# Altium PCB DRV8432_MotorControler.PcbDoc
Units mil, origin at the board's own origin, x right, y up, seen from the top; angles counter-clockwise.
Board outline 2906.47 x 1828.55 mil, 2 copper layers (Top Layer, Bottom Layer); 56 components, 32 nets, 157 pads, 266 vias.
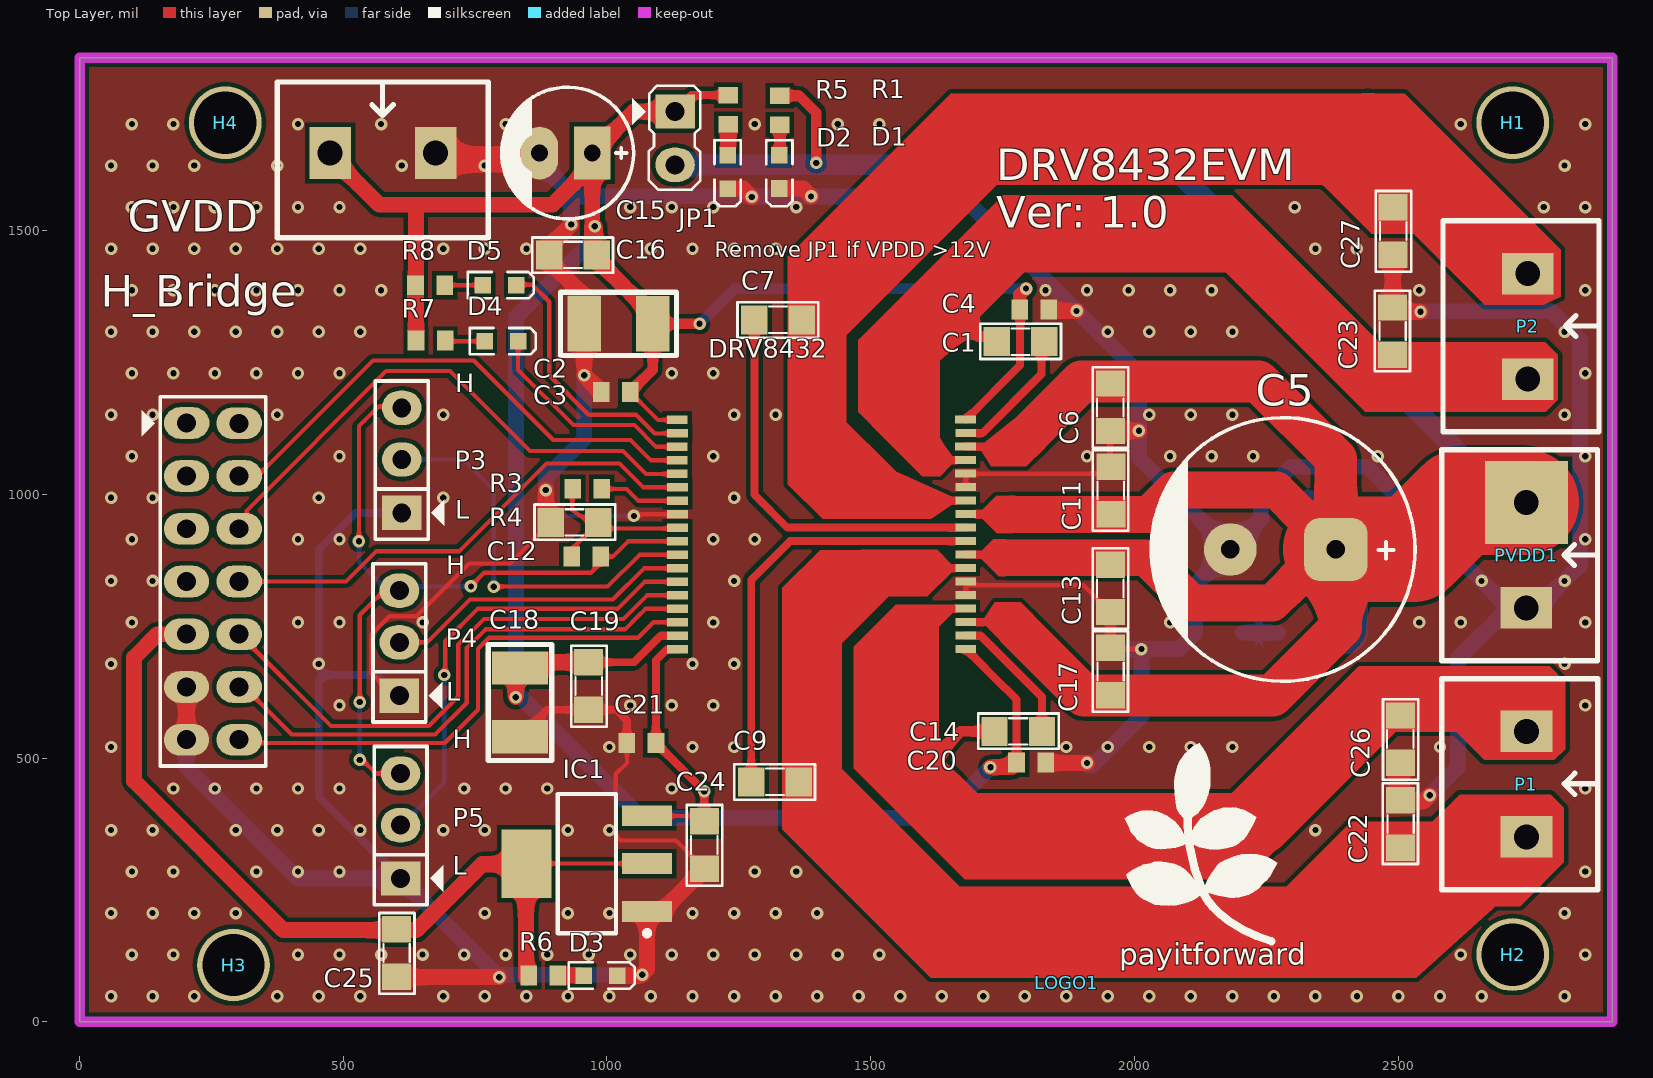
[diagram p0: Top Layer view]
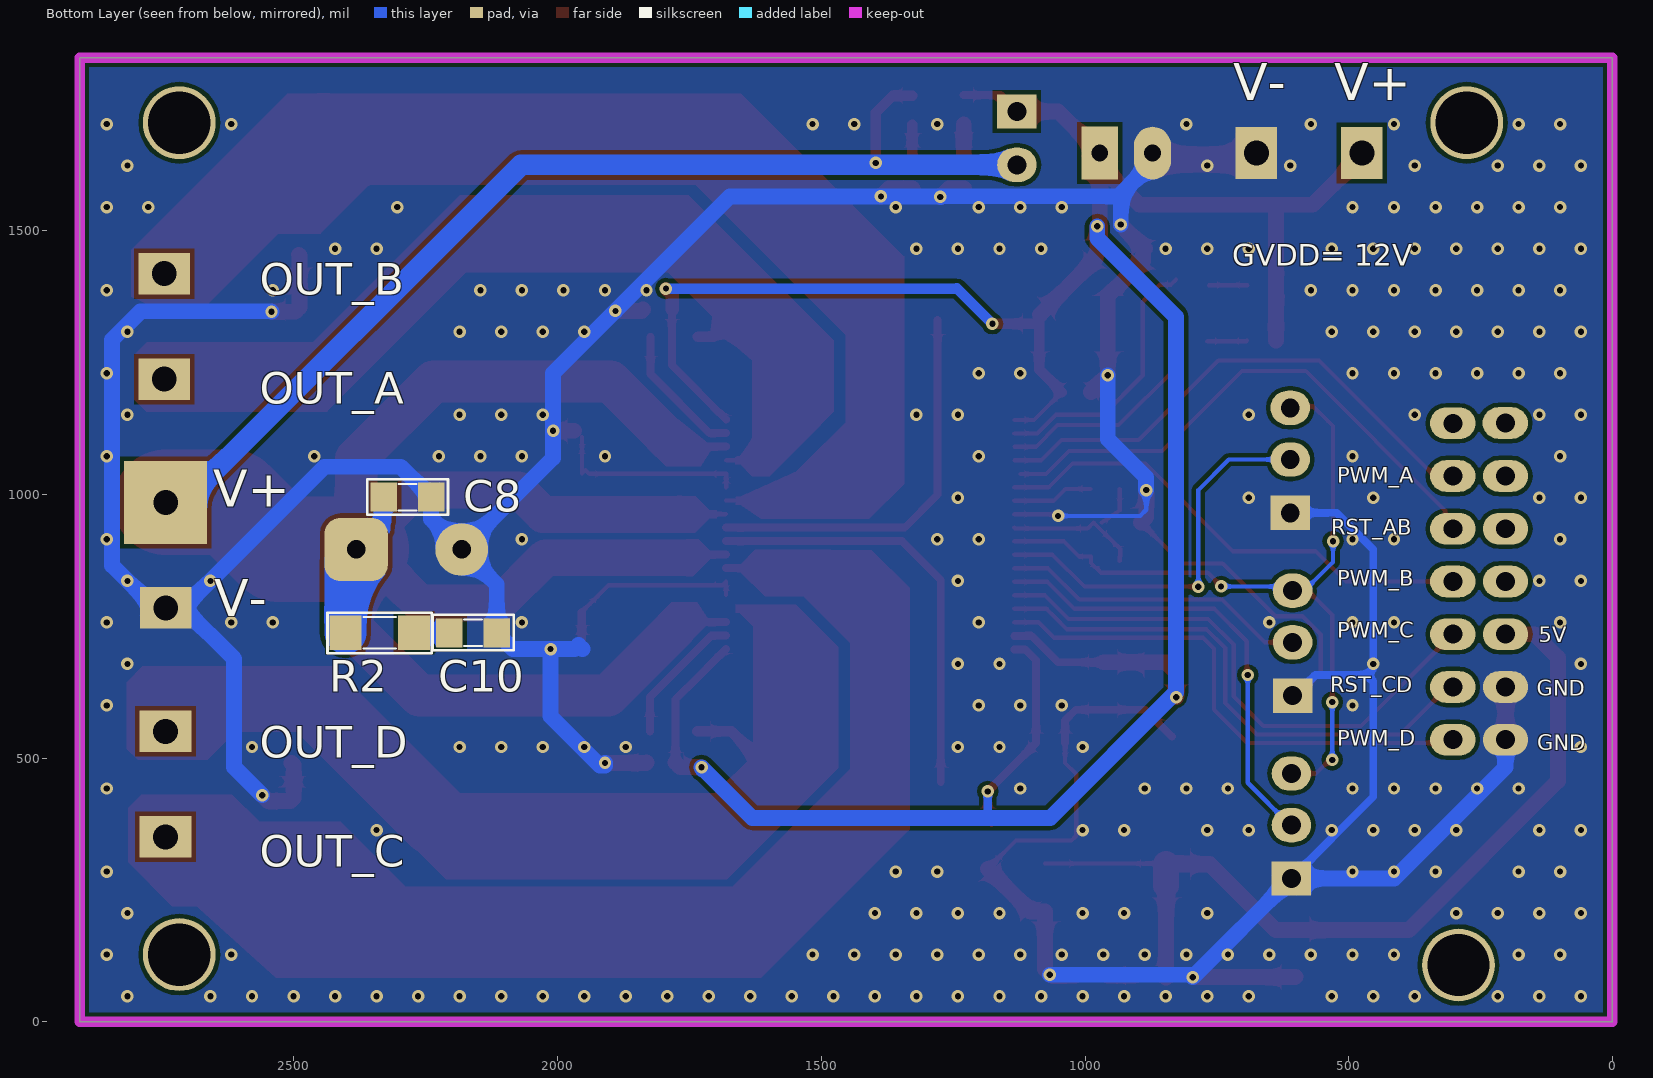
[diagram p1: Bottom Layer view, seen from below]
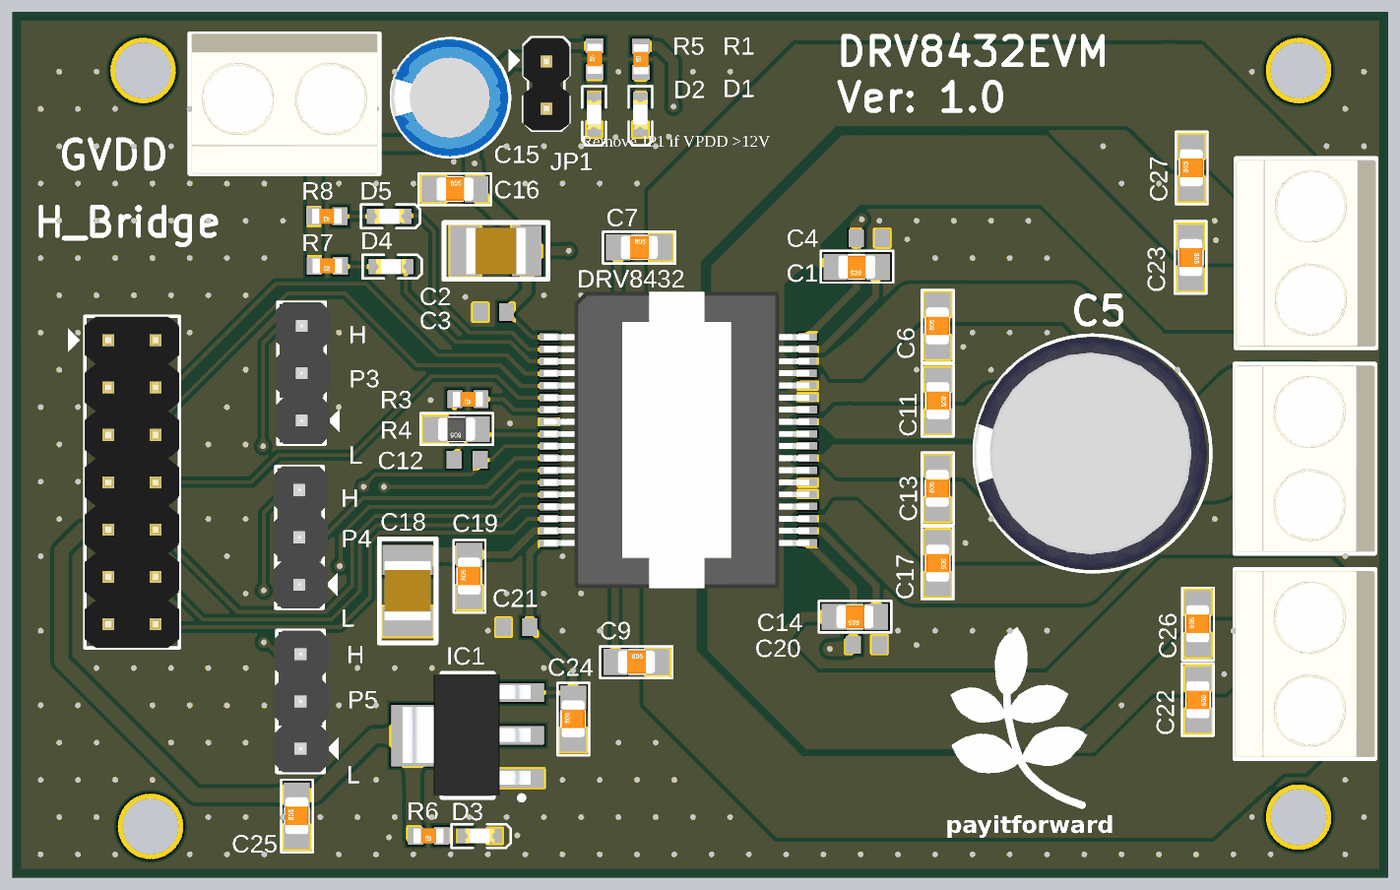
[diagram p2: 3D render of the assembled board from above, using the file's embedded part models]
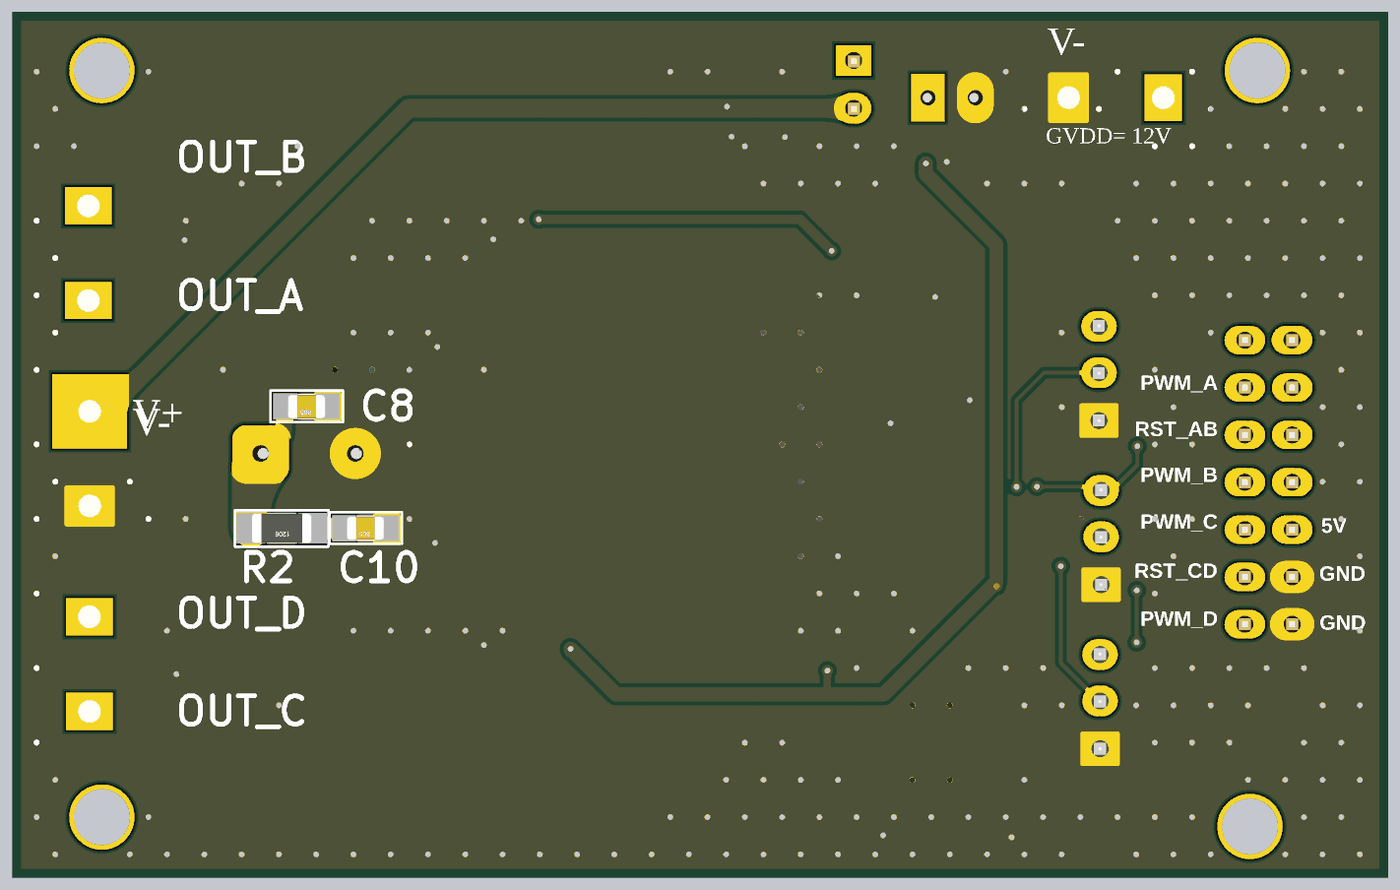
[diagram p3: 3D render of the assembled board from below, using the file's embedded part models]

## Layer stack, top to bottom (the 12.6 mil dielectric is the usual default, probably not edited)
Top Solder: solder mask 0.4, Solder Resist, Dk 3.5
Top Layer: signal copper 1.4
Dielectric 1: dielectric 12.6, FR-4, Dk 4.8
Bottom Layer: signal copper 1.4
Bottom Solder: solder mask 0.4, Solder Resist, Dk 3.5

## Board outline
0,0 2906.46,0 2906.46,1828.55 0,1828.55

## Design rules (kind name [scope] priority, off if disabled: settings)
Clearance [All] p1: gap=8 ignorepadtopadclearanceinfootprint=FALSE
PlaneConnect [All] p1: planeconnectstyle=Direct reliefexpansion=20 reliefentries=4 reliefconductorwidth=10 reliefairgap=10
PolygonConnect [All] p1: connectstyle=Direct reliefconductorwidth=10 reliefentries=4 polygonreliefangle="90 Angle" airgapwidth=10
RoutingVias [All] p1: holewidth=11.81 width=23.62 viastyle="Through Hole" minholewidth=11.81 minwidth=23.62 maxholewidth=196.85 maxwidth=196.85
SolderMaskExpansion [All] p1: expansion=4
Width [All] p1: maxlimit=200 minlimit=8 preferedwidth=15 minimp=50.000000 maximp=50.000000 favimp=50.000000
29 further rules are at their usual default settings.

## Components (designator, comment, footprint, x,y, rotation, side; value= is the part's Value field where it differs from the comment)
C1 "Cap Non-Pol SMD" CAP-SM-0805 1828.93,1289.91 r180 top value=0.1ufd/100V
C2 "Cap Non-Pol SMD" CAP-SM-1210 1021.79,1323.73 r0 top value=100nF
C3 "Cap Non-Pol SMD" CAP-SM-0603 1016.45,1194.2 r180 top value=1ufd/16v
C4 "Cap Non-Pol SMD" CAP-SM-0603 1810.32,1350.89 r0 top value=1ufd/16v
C5 "Cap Pol" CP2/5 2381.98,895.84 r180 top locked value=1000ufd/63V
C6 "Cap Non-Pol SMD" CAP-SM-0805 1954.39,1120.4 r90 top value=0.1ufd/100v
C7 "Cap Non-Pol SMD" CAP-SM-0805 1279.54,1331.26 r0 top value=0.1ufd/100V
C8 "Cap Non-Pol SMD" CAP-SM-0805 2239.92,994.95 r0 bottom value=0.1ufd/100V
C9 "Cap Non-Pol SMD" CAP-SM-0805 1273.52,455.31 r0 top value=0.1ufd/100V
C10 "Cap Non-Pol SMD" CAP-SM-0805 2115.51,737.86 r0 bottom value=0.1ufd/100V
C11 "Cap Non-Pol SMD" CAP-SM-0805 1955.39,1052.4 r270 top value=0.1ufd/100v
C12 "Cap Non-Pol SMD" CAP-SM-0603 960.92,882.33 r180 top value=0.1ufd/16v
C13 "Cap Non-Pol SMD" CAP-SM-0805 1954.39,777.19 r90 top value=0.1ufd/100v
C14 "Cap Non-Pol SMD" CAP-SM-0805 1824.87,550.85 r180 top value=0.1ufd/100V
C15 "Cap Pol" CP1/2.5 972.16,1647.39 r180 top value=330ufd/16v
C16 "Cap Non-Pol SMD" CAP-SM-0805 890.35,1454.35 r0 top value=0.1ufd/16v
C17 "Cap Non-Pol SMD" CAP-SM-0805 1954.89,709.2 r270 top value=0.1ufd/100v
C18 "Cap Non-Pol SMD" CAP-SM-1210 835.1,605.84 r90 top value=100nF
C19 "Cap Non-Pol SMD" CAP-SM-0805 965.35,591.97 r90 top value=0.1ufd/16v
C20 "Cap Non-Pol SMD" CAP-SM-0603 1804.12,491.94 r180 top value=1ufd/16v
C21 "Cap Non-Pol SMD" CAP-SM-0603 1065.35,528.81 r0 top value=1ufd/16v
C22 "Cap Non-Pol SMD" CAP-SM-0805 2504.69,420.47 r270 top value=0.1ufd/16v
C23 "Cap Non-Pol SMD" CAP-SM-0805 2489.54,1354.69 r270 top value=0.1ufd/16v
C24 "Cap Non-Pol SMD" CAP-SM-0805 1184.64,290.38 r90 top value=0.1ufd/16v
C25 "Cap Non-Pol SMD" CAP-SM-0805 601.07,85.63 r90 top value=0.1ufd/16v
C26 "Cap Non-Pol SMD" CAP-SM-0805 2504.34,491.09 r90 top value=0.1ufd/16v
C27 "Cap Non-Pol SMD" CAP-SM-0805 2490.85,1454.48 r90 top value=0.1ufd/16v
D1 "LED SMD" LED_0603_Blue 1326.89,1611.7 r270 top
D2 "LED SMD" LED_0603_Blue 1229,1611.59 r270 top
D3 "LED SMD" LED_0603_Blue 987.79,87.86 r0 top
D4 "LED SMD" LED_0603_Blue 800,1290.7 r0 top
D5 "LED SMD" LED_0603_Blue 796.34,1396.91 r0 top
DRV8432 "DRV8432" PCBComponent_1 1423.58,924.37 r270 top
GVDD "Domino 2" "DOMINO 2- 5mm"#1 575.08,1647.39 r0 top (schematic designator GVDD1)
H1 "Hole" "LO KHOAN 3MM" 2717.32,1704.88 r0 top
H2 "Hole" "LO KHOAN 3MM" 2717.32,127.62 r0 top
H3 "Hole" "LO KHOAN 3MM" 292.01,107.94 r0 top
H4 "Hole" "LO KHOAN 3MM" 276.37,1704.88 r0 top
H_Bridge "Header 7X2" JP7X2 202.75,1135.1 r270 top (schematic designator H_Bridge1)
IC1 "LM1117" SOT223-4N 961.8,300.17 r180 top value=LM317
JP1 "Jumper 2" JP2 1129.23,1726.1 r270 top
LOGO1 "LOGO PIF" "PIF LOGO TOP OVERLAY" 1871.65,74.41 r0 top
P1 "Domino 2" "DOMINO 2- 5mm"#1 2743.51,450.85 r270 top
P2 "Domino 2" "DOMINO 2- 5mm"#1 2745.87,1318.96 r270 top
P3 "Header 3" JP3 610.91,1065.37 r90 top
P4 "Header 3" JP3 606.4,718.72 r90 top
P5 "Header 3" JP3 608.65,372.07 r90 top
PVDD1 "Domino 2" "DOMINO 2- 5mm"#2 2743.12,884.91 r270 top
R1 "RESISTOR SMD" RES-SM-0603 1327.89,1701.64 r90 top value=2K2
R2 "RESISTOR SMD" RES-SM-1206 2272.36,737.86 r0 bottom value="3.3 1/4W"
R3 "RESISTOR SMD" RES-SM-0603 989.45,1010.7 r180 top value=27K
R4 "RESISTOR SMD" RES-SM-0805 983.65,946.99 r180 top value=1-1/4W
R5 "RESISTOR SMD" RES-SM-0603 1230.13,1702.62 r90 top value=2K2
R6 "RESISTOR SMD" RES-SM-0603 906.29,88.25 r180 top value=1K
R7 "RESISTOR SMD" RES-SM-0603 692.57,1291.96 r180 top value=470
R8 "RESISTOR SMD" RES-SM-0603 691.59,1396.91 r180 top value="3.3 1/4W"

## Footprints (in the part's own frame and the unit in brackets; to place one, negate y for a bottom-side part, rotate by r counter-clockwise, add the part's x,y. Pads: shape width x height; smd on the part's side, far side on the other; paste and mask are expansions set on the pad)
CAP-SM-0603 [mm] "SMD Ceramic Capacitor Size 0603"
  rect 0.8x0.95 smd: 1(-0.7,0) 2(0.7,0)
  body extent -0.85,-0.45 0.85,0.45, height 0.6
CAP-SM-0805 [mil]
  rect 50x55 smd: 1(0,0) 2(90,0)
  silkscreen extent -32,-34 121,33, body extent 6,-25 84,25, height 31
CAP-SM-1210 [mil]
  rect 63x106 smd: 1(-65,0) 2(65,0)
  silkscreen extent -110,-60 110,60, body extent -63,-49 63,49, height 51
CP1/2.5 [mil] "Tu hoa 33 >100 uF,50V, 220uF/16V,25V"
  rect 70x100 hole 32: 1(0,0)
  oval 70x100 hole 32: 2(100,0)
  silkscreen extent -78,-125 172,125, body extent -76,-124 172,124, height 422
CP2/5 [mil] "222,50V"
  rrect50% 120x120 hole 35: 1(0,0)
  round 100 hole 35: 2(200,0)
  silkscreen extent -150,-250 350,250, body extent -142,-246 350,246, height 984
"DOMINO 2- 5mm"#1 [mm]
  rect 2x2.5 hole 1.2: 1(-2.54,0) 2(2.54,0)
  silkscreen extent -5.08,-4.08 5.08,3.43, body extent -5,-4.07 5,3.43, height 10
"DOMINO 2- 5mm"#2 [mm]
  rect 4x4 hole 1.2: 1(-2.54,0)
  rect 2x2.5 hole 1.2: 2(2.54,0)
  silkscreen extent -5.08,-4.08 5.08,3.43, body extent -5,-4.07 5,3.43, height 10
JP2 [mil]
  rect 65x75 hole 36: 1(0,0)
  oval 65x75 hole 36: 2(101,0)
  silkscreen extent -49,-81 148,48, body extent -48,-50 148,48, height 323
JP3 [mil] "Jumper 3"
  rect 65x75 hole 36: 1(-100,0)
  oval 65x75 hole 36: 2(1,0) 3(99,0)
  silkscreen extent -150,-81 150,50, body extent -150,-60 150,55, height 355
JP7X2 [mil]
  oval 60x86 hole 36: 1(-0.5,0.5) 2(0,100) 3(100,0) 4(100,100) 5(200,0) 6(200,100) 7(300,0) 8(300,100) 9(400,0) 10(400,100) 11(500,0) 12(500,100) 13(600,0) 14(600,100)
  silkscreen extent -51,-85 650,151, body extent -50,-50 650,150, height 335
LED_0603_Blue [mm] "Chip LED, 2-Leads, Body 1.6x0.8mm, IPC Medium Density"
  rect 0.8x0.8 smd: 1(-0.8,0) 2(0.8,0)
  silkscreen extent -1.52,-0.64 1.65,0.64, body extent -0.8,-0.4 0.8,0.4, height 0.7
"LO KHOAN 3MM" [mil]
  round 138 hole 118.1: 1(0,0)
PCBComponent_1 [mm]
  rect 0.4x1 smd: 1(-5.521,-7.369) 2(-4.871,-7.359) 3(-4.221,-7.369) 4(-3.571,-7.369) 5(-2.921,-7.369) 6(-2.271,-7.359) 7(-1.621,-7.359) 8(-0.971,-7.359) 9(-0.321,-7.359) 10(0.329,-7.359) 11(0.979,-7.359) 12(1.629,-7.359) 13(2.279,-7.359) 14(2.929,-7.359) 15(3.579,-7.359) 16(4.229,-7.359) 17(4.879,-7.359) 18(5.529,-7.359) 19(5.519,6.521) 20(4.869,6.521) 21(4.219,6.521) 22(3.569,6.521) 23(2.919,6.521) 24(2.269,6.521) 25(1.619,6.521) 26(0.969,6.521) 27(0.319,6.521) 28(-0.331,6.521) 29(-0.981,6.521) 30(-1.631,6.521) 31(-2.281,6.521) 32(-2.931,6.511) 33(-3.581,6.511) 34(-4.231,6.511) 35(-4.881,6.521) 36(-5.531,6.511)
  body extent -7.95,-7.63 7.95,6.61, height 3.5
"PIF LOGO TOP OVERLAY" [mil]
  silkscreen extent 110,79 399,454
RES-SM-0603 [mm]
  rect 0.8x0.95 smd: 1(-0.014,0) 2(1.386,0)
  body extent -0.11,-0.4 1.49,0.4, height 0.3
RES-SM-0805 [mil]
  rect 50x55 smd: 1(0,0) 2(90,0)
  silkscreen extent -32,-34 121,33, body extent 6,-25 84,25, height 31
RES-SM-1206 [mil]
  rect 60x65 smd: 1(0,0) 2(130,0)
  silkscreen extent -34,-38 164,39, body extent 2,-31 128,31, height 40
SOT223-4N [mm] "SOT223, 4-Leads, Body 6.5x3.5mm, Pitch 2.3mm, Lead Span 7mm, IPC Medium Density"
  rect 2.4x1 smd: 1(-2.9,2.3) 2(-2.9,0) 3(-2.9,-2.3)
  rect 2.4x3.3 smd: 4(2.9,0)
  silkscreen extent -3.03,-3.35 1.4,3.47, body extent -3.39,-3.27 3.5,3.23, height 1.72

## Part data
C1 C2 C3 C4 C6 C7 C8 C9 C10 C11 C12 C13 C14 C16 C17 C18 C19 C20 C21 C22 C23 C24 C25 C26 C27: "Capacitor"
C5 C15: "Polarized Capacitor (Radial)"
D1 D2 D3 D4 D5: "LED"
DRV8432: library part Component_1
GVDD P1 P2 PVDD1: "Domino, 2-Pin"
H1 H2 H3 H4: "Hole 3mm"
H_Bridge: "Header, 7-Pin, Dual row"
IC1: "Available in 1.8V, 2.5V, 2.85V, 3.3V, 5V, and  Adjustable Versions"
P3 P4 P5: "Header, 3-Pin"
R1 R2 R3 R4 R5 R6 R7 R8: "Resistor"

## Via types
v1: diameter 23.62, hole 11.81, Top Layer to Bottom Layer, tented both sides, 266 vias

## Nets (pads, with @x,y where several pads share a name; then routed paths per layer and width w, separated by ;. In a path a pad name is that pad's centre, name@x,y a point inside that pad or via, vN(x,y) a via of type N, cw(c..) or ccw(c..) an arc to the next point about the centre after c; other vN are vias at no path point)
5V: C25.2 H_Bridge.9 IC1.2 IC1.4 R6.2 | length 1708.4
  Top Layer w8: IC1.4 IC1.2
  Top Layer w30: H_Bridge.9 147.52,735.1 103.54,691.12 103.54,456.76 386.22,174.08 638.47,174.08 763.55,299.16 846.62,299.16 IC1.4 ; R6.2@846.62,84.32 IC1.4@846.62,258.73
  Top Layer w50: IC1.4@846.62,258.73 IC1.4@846.62,299.16
BST_A: C1.1 DRV8432.35 | length 260.5
  Top Layer w15: DRV8432.35@1680.63,1116.36 1711.94,1116.36 1823.89,1228.32 C1.1@1823.89,1299.2
BST_B: C7.1 DRV8432.28 | length 758.5
  Top Layer w15: C7.1 1279.54,999.69 1342,937.23 DRV8432.28@1680.63,937.23
BST_C: C9.1 DRV8432.27 | length 820.4
  Top Layer w15: C9.1 1273.52,838.16 1347,911.64 DRV8432.27@1680.63,911.64
BST_D: C14.1 DRV8432.20 | length 257.7
  Top Layer w15: DRV8432.20@1680.63,732.51 1708.37,732.51 1824.87,616 C14.1
FAULT: D4.2 DRV8432.3 | length 417
  Top Layer w8: D4.2 831.49,1236.43 936.36,1131.56 1052.08,1131.56 1093.26,1090.38 DRV8432.3@1133.77,1090.38
GND: C2.1 C3.2 C4.2 C5.2 C6.1 C8.1 C10.1 C11.1 C13.1 C15.2 C16.1 C17.1 C18.1 C19.1 C20.1 C21.1 C22.1 C23.1 C24.1 C25.1 C26.1 C27.1 D1.2 D2.2 D3.2 DRV8432.8 DRV8432.23 DRV8432.24 DRV8432.31 DRV8432.32 GVDD.2 H_Bridge.11 H_Bridge.13 IC1.1 P3.1 P4.1 P5.1 PVDD1.2 R4.2 | length 11094.8
  Top Layer w8: P4.1 595.66,618.72 553.01,661.37 553.01,734.26 588.04,769.29 639.07,769.29 738.93,869.16 815.82,869.16 R4.2 ; C21.1 1037.79,491.12 1016.73,470.07 1016.73,353.03 1025.6,344.16 1130.86,344.16 C24.1 ; v1(1051.18,959.49) 1054.11,962.43 DRV8432.8@1134.17,962.43 ; DRV8432.23@1680.63,809.28 1680.63,834.87 1687.62,827.87 1903.71,827.87 C13.1 ; DRV8432.31@1680.63,1014 1680.23,1014.4 1680.23,1039.59 1680.63,1039.2 1940.19,1039.2 1947.54,1046.55 1953.89,1040.2 C6.1@1953.89,1109.2 ; C17.1@1959.17,714.4 1966.65,706.92 v1(2013.44,706.92)
  Top Layer w15: C18.1 886.24,591.97 C19.1 1017.53,591.97 1037.79,571.71 C21.1
  Top Layer w15.75: C13.1 1954.39,719.17 C17.1@1959.17,714.4
  Top Layer w30: H_Bridge.13 H_Bridge.11 ; C25.1 601.8,84.9 v1(795.82,84.9) ; v1(883.86,1008.51) 883.86,956.79 R4.2 ; C16.1@886.61,1466.21 v1(932.43,1512.02) ; C16.1 890.35,1442.78 956.79,1376.34 C2.1 v1(956.79,1226.3) C3.2 ; D3.2 1064.04,87.86 1075.98,99.8 IC1.1 1103.88,209.62 C24.1 ; D2.2 1258.51,1580.09 v1(1274.37,1564.23) ; D1.2 1372.03,1580.21 v1(1387.08,1565.16) ; C20.1 1832.53,491.09 v1(1910.23,491.09) ; C4.2 1840.67,1348.1 v1(1890.55,1348.1) ; C6.1@1969.29,1121.07 v1(2008.66,1121.07) ; C27.1 2489.54,1453.17 C23.1 2497.68,1346.56 v1(2542.55,1346.56) ; C26.1 2500.43,487.18 2500.43,424.73 C22.1 2506.52,418.64 2548.97,418.64 v1(2559.97,429.64)
  Top Layer w50: GVDD.2@682.42,1635.31 860.08,1635.31 C15.2
  Bottom Layer w8: 538.89,961.4 606.94,961.4 P3.1 ; v1(883.86,1008.51) 883.86,971.16 895.52,959.49 v1(1051.18,959.49)
  Bottom Layer w15: P4.1@602.38,618.72 563.33,657.77 465.79,657.77 ; P5.1 453.54,427.18 453.54,645.52 465.79,657.77 ; P3.1 523.17,965.37 453.54,895.73 453.54,670.02 465.79,657.77
  Bottom Layer w20: P4.1@602.38,618.72 P4.1
  Bottom Layer w30: H_Bridge.13 202.75,483.16 413.85,272.07 P5.1 v1(795.82,84.9) 800.33,89.41 v1(1066.94,89.41) ; C15.2 872.16,1629.86 932.43,1569.6 ; v1(883.86,1008.51) 884.35,1009 884.35,1032.84 956.79,1105.29 v1(956.79,1226.3) ; v1(932.43,1512.02) 932.43,1569.6 ; v1(1910.23,491.09) 1910.23,485.93 1919.79,485.93 2013.44,579.58 v1(2013.44,706.92) ; 1952.61,706.92 1960.38,714.68 1968.14,706.92 v1(2013.44,706.92) ; v1(2542.55,1346.56) 2543.57,1347.57 2790.69,1347.57 2844.86,1293.4 2844.86,865.65 2764.11,784.91 PVDD1.2 PVDD1.2@2709.84,784.91 ; v1(2559.97,429.64) 2613.35,483.03 2613.35,688.42 PVDD1.2@2709.84,784.91 ; 932.43,1569.6 936.83,1565.2 958.6,1565.2 958.81,1565.41 1273.19,1565.41 v1(1274.37,1564.23) 1275.34,1565.2 1673.44,1565.2 v1(1890.55,1348.1) 2008.66,1229.99 v1(2008.66,1121.07) 2008.66,1069.17 C5.2 ; v1(2013.44,706.92) 2084.56,706.92 C10.1 2115.51,829.36 C5.2 ; C5.2 2239.92,953.77 C8.1 2297.79,1052.82 2441.92,1052.82 PVDD1.2@2709.84,784.91
  other v1: 59.84,48.89 138.58,48.89 217.32,48.89 374.8,48.89 453.54,48.89 532.28,48.89 689.76,48.89 768.5,48.89 847.24,48.89 925.98,48.89 1004.72,48.89 1083.46,48.89 1162.2,48.89 1240.94,48.89 1319.68,48.89 1398.42,48.89 1477.16,48.89 1555.9,48.89 1634.64,48.89 1713.38,48.89 1792.12,48.89 1870.86,48.89 1949.6,48.89 2028.34,48.89 2107.08,48.89 2185.82,48.89 2264.56,48.89 2343.31,48.89 2422.05,48.89 2500.79,48.89 2579.53,48.89 2658.27,48.89 2815.75,48.89 99.21,127.63 177.95,127.63 414.17,127.63 492.91,127.63 571.65,127.63 650.39,127.63 729.13,127.63 807.87,127.63 886.61,127.63 965.35,127.63 1044.09,127.63 1122.83,127.63 1201.57,127.63 1280.31,127.63 1359.05,127.63 1437.79,127.63 1516.53,127.63 2618.9,127.63 2855.12,127.63 59.84,206.37 138.58,206.37 217.32,206.37 296.06,206.37 768.5,206.37 925.98,206.37 1004.72,206.37 1162.2,206.37 1240.94,206.37 1319.68,206.37 1398.42,206.37 2815.75,206.37 99.21,285.11 177.95,285.11 335.43,285.11 414.17,285.11 492.91,285.11 1280.31,285.11 1359.05,285.11 2855.12,285.11 59.84,363.85 138.58,363.85 296.06,363.85 374.8,363.85 453.54,363.85 532.28,363.85 689.76,363.85 768.5,363.85 925.98,363.85 1004.72,363.85 2343.31,363.85 177.95,442.59 256.69,442.59 335.43,442.59 414.17,442.59 492.91,442.59 729.13,442.59 807.87,442.59 886.61,442.59 1122.83,442.59 2855.12,442.59 59.84,521.33 1004.72,521.33 1162.2,521.33 1240.94,521.33 1870.86,521.33 1949.6,521.33 2028.34,521.33 2107.08,521.33 2185.82,521.33 2579.53,521.33 492.91,600.07 1044.09,600.07 1122.83,600.07 1201.57,600.07 2855.12,600.07 59.84,678.81 453.54,678.81 1162.2,678.81 1240.94,678.81 2815.75,678.81 99.21,757.55 414.17,757.55 492.91,757.55 650.39,757.55 1201.57,757.55 2067.71,757.55 2540.16,757.55 2618.9,757.55 2855.12,757.55 59.84,836.29 138.58,836.29 1240.94,836.29 2658.27,836.29 2815.75,836.29 99.21,915.03 414.17,915.03 492.91,915.03 1201.57,915.03 1280.31,915.03 2067.71,915.03 2855.12,915.03 59.84,993.77 138.58,993.77 453.54,993.77 689.76,993.77 1240.94,993.77 99.21,1072.51 492.91,1072.51 1201.57,1072.51 1910.23,1072.51 2067.71,1072.51 2146.45,1072.51 2225.19,1072.51 2461.42,1072.51 2855.12,1072.51 59.84,1151.25 138.58,1151.25 374.8,1151.25 689.76,1151.25 1240.94,1151.25 1319.68,1151.25 2028.34,1151.25 2107.08,1151.25 2185.82,1151.25 2815.75,1151.25 99.21,1229.99 177.95,1229.99 256.69,1229.99 335.43,1229.99 414.17,1229.99 492.91,1229.99 1122.83,1229.99 1201.57,1229.99 2855.12,1229.99 59.84,1308.73 138.58,1308.73 217.32,1308.73 296.06,1308.73 374.8,1308.73 453.54,1308.73 532.28,1308.73 1949.6,1308.73 2028.34,1308.73 2107.08,1308.73 2185.82,1308.73 2815.75,1308.73 99.21,1387.47 177.95,1387.47 256.69,1387.47 335.43,1387.47 414.17,1387.47 492.91,1387.47 571.65,1387.47 1831.49,1387.47 1910.23,1387.47 1988.97,1387.47 2067.71,1387.47 2146.45,1387.47 2540.16,1387.47 2855.12,1387.47 59.84,1466.21 138.58,1466.21 217.32,1466.21 296.06,1466.21 374.8,1466.21 453.54,1466.21 532.28,1466.21 689.76,1466.21 768.5,1466.21 847.24,1466.21 1083.46,1466.21 1162.2,1466.21 1240.94,1466.21 1319.68,1466.21 2343.31,1466.21 2422.05,1466.21 99.21,1544.95 177.95,1544.95 256.69,1544.95 335.43,1544.95 414.17,1544.95 492.91,1544.95 1044.09,1544.95 1122.83,1544.95 1201.57,1544.95 1359.05,1544.95 2303.93,1544.95 2776.38,1544.95 2855.12,1544.95 59.84,1623.69 138.58,1623.69 217.32,1623.69 374.8,1623.69 611.02,1623.69 768.5,1623.69 2815.75,1623.69 99.21,1702.43 177.95,1702.43 414.17,1702.43 571.65,1702.43 807.87,1702.43 1280.31,1702.43 1437.79,1702.43 1516.53,1702.43 2618.9,1702.43 2855.12,1702.43
GVDD: C2.2 C3.1 C4.1 C15.1 C16.2 C18.2 C19.2 C20.2 C21.2 C24.2 DRV8432.1 DRV8432.17 DRV8432.18 DRV8432.19 DRV8432.36 GVDD.1 IC1.3 JP1.1 R5.2 R7.2 R8.2 | length 6023.1
  Top Layer w8: 658.89,1549.36 660.16,1548.09 ; C3.1 1096.65,1141.56 DRV8432.1@1133.77,1141.56 ; IC1.3 1160.07,390.72 C24.2@1177.53,373.27 ; C2.2@1085.48,1323.73 C2.2@1085.48,1340.9
  Top Layer w15: C19.2 1051.19,681.97 1101.33,732.11 DRV8432.17@1134.17,732.11 ; C21.2 1092.91,685.73 1113.7,706.52 DRV8432.18@1134.17,706.52 ; JP1.1 1160.31,1757.18 R5.2 ; DRV8432.36@1680.23,1141.95 1783.39,1245.12 C4.1@1783.39,1338.28 ; DRV8432.19@1680.63,706.92 1754.81,632.73 1755.52,632.73 1776.56,611.69 C20.2
  Top Layer w15.75: C21.2 v1(1184.58,437.14) C24.2 C24.2
  Top Layer w20: C3.1 1086.79,1236.98 C2.2 v1(1175.58,1323.73)
  Top Layer w25: C4.1 1782.76,1378.72 v1(1794.6,1390.55)
  Top Layer w30: GVDD.1@482.42,1635.31 568.37,1549.36 638.01,1549.36 ; R7.2 638.01,1549.36 ; v1(827.2,615.52) 827.2,662.93 C18.2 846.24,681.97 C19.2 ; C15.1 1050.87,1726.1 JP1.1 ; v1(976.75,1508.6) 976.75,1467.97 C16.2@972.16,1463.38 ; C2.2@1085.48,1340.9 980.35,1446.03 C16.2 C16.2@972.16,1462.54 ; v1(1727.1,482.96) 1767.59,482.96 C20.2 ; 638.01,1549.36 658.89,1549.36 896.82,1549.36 972.16,1624.7 C16.2@972.16,1463.38 ; C16.2@972.16,1462.54 C16.2@972.16,1463.38 ; C16.2@972.16,1462.54 971.74,1462.96 C16.2@972.16,1463.38
  Bottom Layer w15.75: v1(1184.58,437.14) 1184.58,388.57 1186.4,386.75
  Bottom Layer w20: v1(1175.58,1323.73) 1242.89,1391.04 1243.38,1390.55 v1(1794.6,1390.55)
  Bottom Layer w30: v1(976.75,1508.6) 976.75,1486.16 827.77,1337.17 827.77,624.84 1065.86,386.75 1186.4,386.75 1630.88,386.75 v1(1727.1,482.96) ; v1@1724.45,478.21 v1@1725.57,479.33
M1: DRV8432.13 P5.2 | length 906.4
  Top Layer w8: v1(691.59,657.77) 693.34,657.77 693.34,721.76 754.88,783.29 1019.96,783.29 1071.14,834.47 DRV8432.13@1134.17,834.47
  Bottom Layer w8: P5.2@576.18,372.9 611.09,372.9 691.59,453.4 v1(691.59,657.77)
M2: DRV8432.12 P4.2 | length 585.9
  Top Layer w8: P4.2 658.98,719.72 740.37,801.11 1011.09,801.11 1070.05,860.07 DRV8432.12@1134.17,860.07
M3: DRV8432.11 P3.2 | length 758.9
  Top Layer w8: v1@781.88,825.48 1001.3,825.48 1061.47,885.66 DRV8432.11@1134.17,885.66
  Bottom Layer w8: P3.2 727.44,1066.37 785.17,1008.63 v1(785.17,825.11)
NetC10_2: C10.2 R2.1 | length 66.9
  Bottom Layer w30: C10.2 R2.1
NetC12_2: C12.2 DRV8432.9 R3.2 R4.1 | length 331.2
  Top Layer w8: C12.2 933.36,896.7 R4.1 994.96,935.68 1133.01,935.68 DRV8432.9@1134.17,936.84 ; C12.2@934.25,874.2 C12.2@934.25,882.33 ; R3.2@934.33,1010.7 934.33,970.16 R4.1@968.56,946.99
NetD1_1: D1.1 R1.1 | length 58.3
  Top Layer w20: D1.1 1327.89,1644.2 R1.1
NetD2_1: D2.1 R5.1 | length 59.4
  Top Layer w30: D2.1 1230.13,1644.21 R5.1
NetD3_1: D3.1 R6.1 | length 49.6
  Top Layer w30: R6.1 955.9,88.25 D3.1
NetD4_1: D4.1 R7.1 | length 75.9
  Top Layer w8: R7.1 694.4,1290.7 D4.1
NetD5_1: D5.1 R8.1 | length 72.7
  Top Layer w8: R8.1 D5.1
NetDRV8432_7: DRV8432.7 R3.1 | length 154.1
  Top Layer w8: R3.1@989.45,1010.7 1037.4,1010.7 1060.07,988.02 DRV8432.7@1134.17,988.02
OTW: D5.2 DRV8432.2 | length 508.8
  Top Layer w8: D5.2@827.55,1407.15 836.79,1397.92 858.02,1397.92 890.49,1365.45 890.49,1226.11 965.35,1151.25 1055.3,1151.25 1090.58,1115.97 DRV8432.2@1134.17,1115.97
OUT_A: C1.2 C23.2 DRV8432.33 P2.2 | length 1790.5
  Top Layer w8: 1565.17,1137.56 1637.55,1065.18 DRV8432.33@1680.23,1065.18 ; 1575.07,1220.38 1589.69,1235 ; 1663.89,1309.2 1693.89,1309.2
  Top Layer w20: 1654.45,1348.79 1704.03,1299.2 C1.2@1733.89,1299.2
  Top Layer w100: 1565.17,1137.56 1565.17,1259.51 1654.45,1348.79 1654.45,1394.28 1739.36,1479.2 2204.01,1479.2 2464.25,1218.96 P2.2@2712.59,1218.96
OUT_B: C7.2 C27.2 DRV8432.30 P2.1 | length 2972.5
  Top Layer w8: 1554.99,988.41 DRV8432.30@1680.63,988.41
  Top Layer w100: 1511.4,1009.85 1404.59,1116.66 1404.59,1323 1737.3,1655.71 2379.62,1655.71 ; C27.2 2379.62,1655.71 ; 2498.29,1655.71 P2.1@2712.59,1441.4 ; P2.1@2712.59,1418.96 P2.1@2712.59,1436.13 ; 2379.62,1655.71 2493.01,1655.71 ; 2493.01,1655.71 P2.1@2712.59,1436.13 ; 2493.01,1655.71 2437.27,1711.45 2449.15,1711.45 2712.59,1448.01 P2.1@2712.59,1441.4 ; P2.1@2712.59,1436.13 P2.1@2712.59,1441.4
OUT_C: C9.2 C22.2 DRV8432.25 P1.2 | length 2130.3
  Top Layer w15: 1492.9,835.53 1517.83,860.46 DRV8432.25@1680.63,860.46
  Top Layer w100: 1492.9,835.53 1385.66,728.29 1385.66,449.32 1648.59,186.39 2360.62,186.39 C22.2 2689.85,330.47 P1.2@2710.23,350.85
OUT_D: C14.2 C26.2 DRV8432.22 P1.1 | length 1734.1
  Top Layer w20: 1580.47,460.54 1670.77,550.85 C14.2
  Top Layer w100: 1527.98,686.24 1527.98,513.03 1580.47,460.54 1672.73,368.28 2243.23,368.28 2487.61,612.66 2648.42,612.66 P1.1@2710.23,550.85
PVDD: C5.1 C6.2 C8.2 C11.2 C13.2 C17.2 DRV8432.21 DRV8432.26 DRV8432.29 DRV8432.34 JP1.2 PVDD1.1 R1.2 R2.2 | length 6320.7
  Top Layer w8: DRV8432.29@1680.63,962.82 1768.5,962.82 ; 1731.26,886.05 1750.87,886.05 ; 1756.72,880.2 1769.73,867.19
  Top Layer w15: DRV8432.34@1680.23,1090.77 1789.77,1090.77 ; DRV8432.21@1680.63,758.1 1750,758.1 1772.91,735.18 ; DRV8432.26@1680.63,886.05 1731.26,886.05 ; 1819.07,1090.77 C6.2@1927.49,1199.2
  Top Layer w20: R1.2 1364.89,1756.2 1396.89,1724.2 1396.64,1723.94 v1(1396.64,1628.72)
  Top Layer w50: C5.1@2381.98,926.94 C5.1@2384.98,929.94
  Top Layer w70: 1756.72,880.2 2023.53,880.2 2109.29,794.44 2261.38,794.44 C5.1@2372.38,905.44 ; 1768.5,962.82 1768.92,962.4 C11.2 ; C11.2@1956.79,962.4 2027.68,962.4 2073.82,1008.54 2269.28,1008.54 2324.08,953.74
  Top Layer w80: 1776.69,746.99 1904.48,619.2 C17.2 2001.41,619.2 2001.18,618.96 2262.19,618.96 2391.26,748.03 C5.1@2386.16,895.84 ; 1789.77,1104.2 1899.77,1214.2 2235.61,1214.2 2381.98,1067.82 C5.1@2381.98,926.94 ; C5.1@2384.98,929.94 2385.26,921.69 C5.1@2385.26,896.73
  Top Layer w150: PVDD1.1@2682.46,985.72 PVDD1.1@2737.46,985.72
  Top Layer w200: C5.1 2386.16,895.84 C5.1@2385.26,896.73 ; C5.1@2411.12,895.84 2528.45,895.84 2617.52,984.91 PVDD1.1
  Bottom Layer w30: C8.2 2330.86,994 2330.86,946.96 C5.1
  Bottom Layer w39.37: JP1.2 2069.65,1625.1 PVDD1.1@2709.84,984.91
  Bottom Layer w80: C5.1 2402.36,875.46 R2.2
PWM_A: DRV8432.4 H_Bridge.4 | length 1000.2
  Top Layer w8: H_Bridge.4 337.32,1035.1 556.39,1254.18 747.35,1254.18 898.13,1103.39 1044.74,1103.39 1083.35,1064.79 DRV8432.4@1133.77,1064.79
PWM_B: DRV8432.6 H_Bridge.8 | length 942.7
  Top Layer w8: H_Bridge.8 505.22,835.1 562.42,892.31 719.23,892.31 885.6,1058.68 1023.89,1058.68 1068.96,1013.61 DRV8432.6@1134.17,1013.61
PWM_C: DRV8432.14 H_Bridge.10 | length 1063.9
  Top Layer w8: H_Bridge.10 476.82,561.04 662.11,561.04 718.13,617.06 718.13,715.54 766.81,764.22 1031.08,764.22 1075.75,808.88 DRV8432.14@1134.17,808.88
PWM_D: DRV8432.16 H_Bridge.14 | length 996.4
  Top Layer w8: H_Bridge.14 308.82,529.04 692.57,529.04 755.5,591.97 755.5,707.66 776.26,728.42 1059.06,728.42 1088.34,757.7 DRV8432.16@1134.17,757.7
RESET_AB: DRV8432.5 H_Bridge.6 | length 1056.8
  Top Layer w8: H_Bridge.6 325.98,935.1 317.18,943.9 317.18,969.83 581.38,1234.02 702.41,1234.02 854.14,1082.3 1030.66,1082.3 1074.23,1038.72 DRV8432.5@1122.09,1038.72
RESET_CD: DRV8432.15 H_Bridge.12 | length 1028.4
  Top Layer w8: H_Bridge.12 312.25,635.1 402.32,545.04 674.25,545.04 734.13,604.92 734.13,708.92 769.64,744.42 1034.03,744.42 1059.32,769.71 1059.32,769.83 1072.78,783.29 DRV8432.15@1134.17,783.29
V_REG: C12.1 DRV8432.10 P3.3 P4.3 P5.3 | length 1425.4
  Top Layer w8: v1(529.78,911.2) 529.78,1129.67 538.67,1138.57 538.75,1138.49 567.37,1167.12 P3.3@582.08,1167.12 ; v1(531.18,496.86) 536.43,496.86 562.22,471.07 P5.3 ; v1(531.18,606.51) 531.18,771.4 577.5,817.72 P4.3 ; v1(742.06,825.76) 742.06,826.47 767.22,851.63 969.79,851.63 988.48,870.33 C12.1 1011.23,882.33 1040.15,911.25 DRV8432.10@1134.17,911.25
  Bottom Layer w8: v1(529.78,911.2) 529.78,871.72 P4.3@575.08,826.42 ; v1(531.18,496.86) v1(531.18,606.51) ; P4.3 619.8,831.11 625.14,825.76 v1(742.06,825.76)
pads on no net: H1.1 H2.1 H3.1 H4.1 H_Bridge.1 H_Bridge.2 H_Bridge.3 H_Bridge.5 H_Bridge.7

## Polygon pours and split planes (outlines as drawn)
GND on Top Layer (solid, remove dead copper, pour order 88): 0.05,0.05 2906.51,0.05 2906.51,1828.5 0.05,1828.5
no net on Top Layer "Top Layer-No Net 4" (solid, remove dead copper, pour order 14): 1773.89,997.2 1738.39,997.2 1711.35,970.16 1698.09,970.16 1698.09,955.2 1711.39,955.2 1739.39,927.2 1769.89,927.2
no net on Top Layer "Top Layer-No Net 8" (solid, remove dead copper, pour order 42): 1524.79,1107.42
no net on Top Layer "Top Layer-No Net 3" (solid, remove dead copper, pour order 22): 1750,915.2
no net on Top Layer "Top Layer-No Net 1" (solid, remove dead copper, pour order 6): 1621.47,962.14
no net on Top Layer "Top Layer-No Net" (solid, remove dead copper, pour order 4): 1933.89,619.2
GND on Bottom Layer (solid, remove dead copper, pour order 86): 0.05,1828.5 0.05,0.05 2906.51,0.05 2906.51,1828.5

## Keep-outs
Keep-Out Layer:
  the board outline again, w20

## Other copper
Top Layer:
  region net OUT_B: 1544.43,1045.08 1544.43,1000.65 1497.56,953.77 1408.8,953.8 1342.99,1019.84 1342.99,1451.32 1343.6,1451.32 1652.69,1760.41 2512.65,1760.07 2808.25,1464.47 2808.25,1374.55 2776.33,1359.92 2664.53,1359.92 2529.18,1495.28 2528.46,1494.57 2449.32,1494.57 2449.32,1495.27 2356.95,1587.64 1737.6,1587.64 1737.6,1585.46 1453.92,1301.78 1453.92,1135.68 1545.01,1044.59
  region net OUT_C: 2616.51,431.16 2789.26,431.16 2814.16,406.27 2814.16,302.41 2731.47,219.72 2684.87,219.72
  region net OUT_D: 1547.14,790.93 1467.95,711.74 1467.95,480.63 1677.95,270.63 2212.43,270.63 2492.31,550.5 2610,550.5 2663.85,496.66 2796.54,496.66 2817.33,517.45 2817.33,644.12 2787.25,674.21 2425.55,674.21 2184.62,433.28 1701.99,433.28 1629.55,505.72 1629.55,772.7 1564.75,787.03
  region net OUT_C: 1485.97,894.82 1404.19,894.82 1332.76,823.38 1332.76,365.61 1614.38,83.99 2534.89,83.98 2805.8,328.46 2789.2,413.83 2725.07,431.16 2616.51,431.16 2564.92,379.58 2411.18,379.58 2287.74,256.14 1669.38,256.14 1445.57,479.95 1445.57,732.21 1449.32,732.21 1497.63,780.52
  region net OUT_A: 1528.12,1105.18 1476.74,1156.56 1476.74,1292.95 1751.17,1567.38 2185.93,1567.38 2464.45,1288.86 2778.67,1288.86 2802.79,1264.74 2802.78,1179.53 2780.04,1156.79 2436.4,1156.79 2436.4,1157.68 2172.81,1421.26 1791.13,1421.26 1630.76,1260.9 1630.76,1098.9
  region net OUT_A: 1514.55,1137.18
  region net PVDD: 1742.44,726.82 1718.35,750.91 1714.95,765.53 1735.5,795.92 1784.17,795.92 1808.89,771.2
  region net PVDD: 1755.89,915.2 1732.89,915.2 1707.89,890.2 1707.89,879.75 1742.44,845.2 1755.89,845.2
  region net PVDD: 1743.89,912.23
  region net PVDD: 1773.89,997.2 1738.39,997.2 1711.35,970.16 1698.09,970.16 1698.09,955.2 1711.39,955.2 1739.39,927.2 1769.89,927.2
  region net PVDD: 1771.74,1142.45 1715.65,1098.61 1695.52,1098.61 1695.52,1082.91 1709.76,1082.91 1728.75,1053.27 1794.97,1053.27 1829.89,1088.2
  region net OUT_D: 1577.16,690.41 1577.16,697.43 1655.78,776.05 1661.99,776.05 1661.99,791.56 1660.15,790.93 1547.14,790.93 1478.03,721.82 1478.03,675.19
  region net OUT_D: 1635.07,758.11
  region net OUT_C: 1533.17,806.66 1607.59,806.66 1653.31,852.38 1660.58,852.38 1660.58,868.32 1653.11,868.18 1625.95,895.34 1482.49,895.34 1454.42,867.27
  region net OUT_B: 1481.52,969.81 1497.56,953.77 1614.56,953.77 1654.11,980.95 1662,980.95 1662,995.43 1661.32,996.11 1654.69,996.11 1544.43,1045.08
  region net OUT_B: 1494.82,963.55
  region net OUT_A: 1524.79,1107.42 1597.39,1034.82 1631.65,1034.82 1654.16,1057.33 1662.86,1057.33 1662.86,1070.72 1660.82,1072.76 1654.91,1072.76 1638.7,1094.88 1614.16,1134.71
  region net OUT_A: 1614.55,1132.94
  region: 1661.67,1073.73
  region: 1661.67,1073.73
  region net OUT_A: 2610.84,1256.08
  region net OUT_B: 1654.59,999.39
  region: 1663.14,996.28
  region: 1661.32,996.11
  region: 1660.69,996.4
  region: 1660.69,996.4
  region net PVDD: 1738.59,846.1
  region: 1947.69,883.4
  region net PVDD: 1949.89,882.9
  region net PVDD: 1700.29,1083.4
  region net PVDD: 1954.69,1207
  region: 1957.89,1253.6

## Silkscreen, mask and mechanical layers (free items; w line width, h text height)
Top Overlay:
  text "DRV8432EVM / Ver: 1.0" at 1737.79,1505.5 h60
  text "Remove JP1 if VPDD >12V" at 1204.72,1439.37 h50
  text "H /  /  /  / L" at 712.27,941.82 h60
  text "H /  /  /  / L" at 695.75,596.77 h60
  text "H /  /  /  / L" at 707.8,266.41 h60
Bottom Overlay:
  text "V+" at 527.67,1723.57 h120
  text "V-" at 718.57,1723.57 h120
  text "GVDD= 12V" at 721.26,1419.68 h70
  text "OUT_B" at 2565.12,1378.43 h60
  text "OUT_A" at 2565.12,1171.9 h60
  text "PWM_A" at 521.8,1011.75 h50
  text "V+" at 2653.01,953.53 h120
  text "RST_AB" at 533.59,913.77 h50
  text "PWM_B" at 521.8,816.95 h50
  text "V-" at 2650.97,745.76 h120
  text "PWM_C" at 521.8,717.76 h50
  text "5V" at 139.73,709.49 h50
  text "RST_CD" at 534.71,614.31 h50
  text "GND" at 143.85,608.34 h50
  text "PWM_D" at 521.8,513.25 h50
  text "GND" at 143.01,504.72 h50
  text "OUT_D" at 2565.12,501 h60
  text "OUT_C" at 2565.12,294.47 h60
